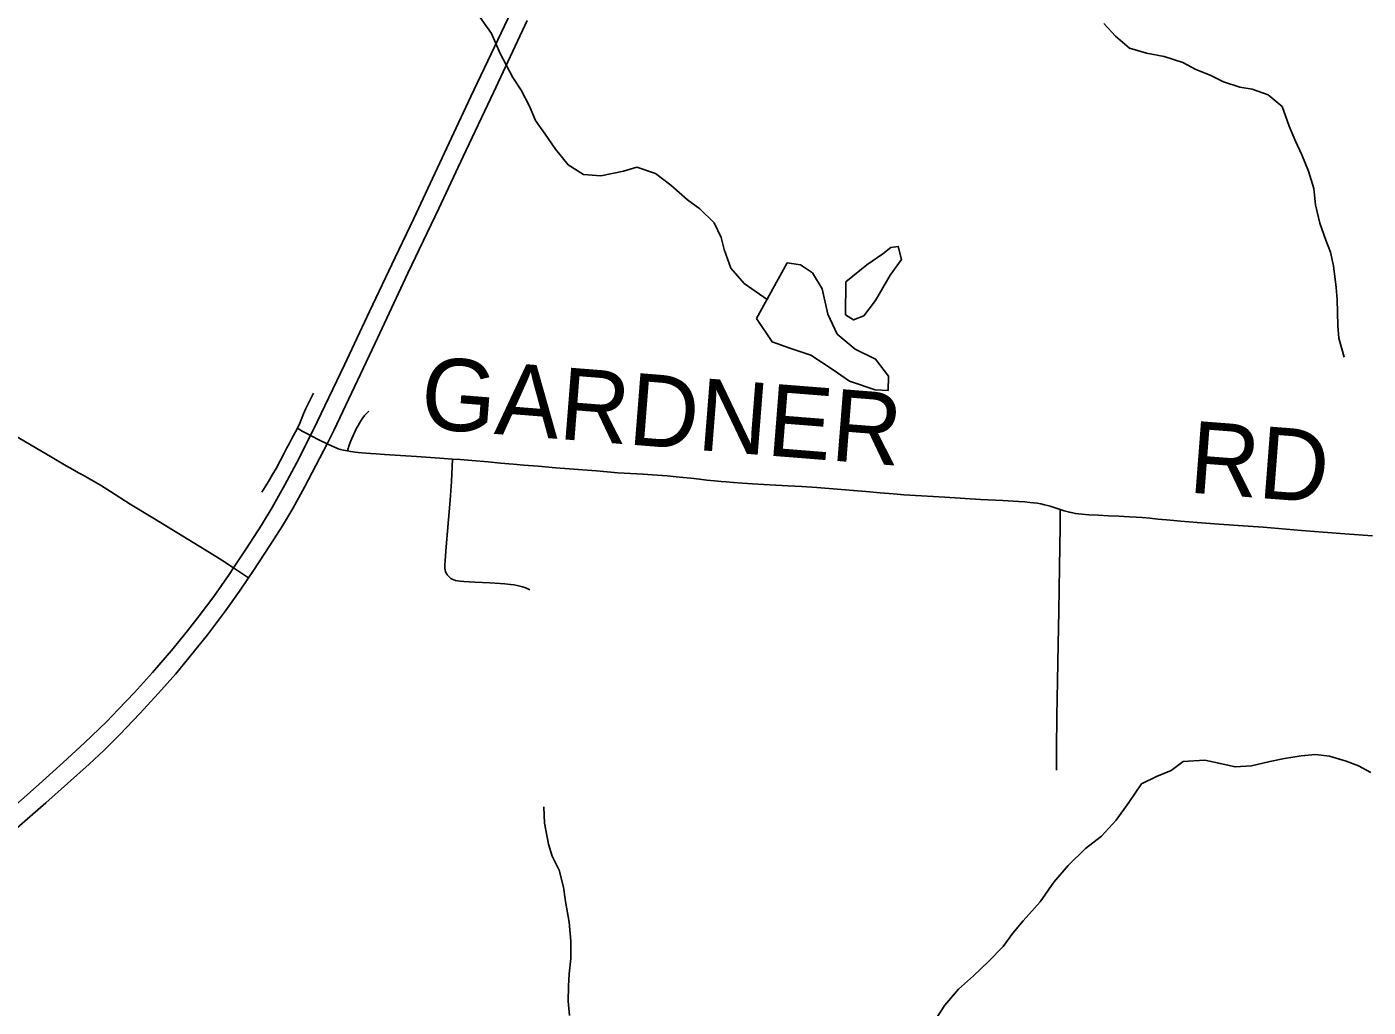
# Model space of a CAD drawing. Extents: x 1451455 to 1749751, y 218250 to 574981.
# Drawn here: x 1595698 to 1601288, y 286670 to 290756 of the extents above; entities that cross this region are included whole.
import ezdxf

# ---------------------------------------------------------------- set-up
doc = ezdxf.new("R2010")
doc.units = 0
for name, color, linetype in [('GM_X_Minor_Lake', 7, 'Continuous'), ('GM_X_Minor_River', 7, 'Continuous'), ('GM_X_Township_Road', 7, 'Continuous'), ('GM_X_Township_Road_Text', 7, 'Continuous'), ('GM_X_Township_ROW', 7, 'Continuous'), ('GM_X_US_Route', 7, 'Continuous')]:
    doc.layers.add(name, color=color, linetype=linetype)

msp = doc.modelspace()

# ---------------------------------------------------------------- linework, layer by layer
at = {"layer": 'GM_X_Minor_Lake'}
for points in [[(1599109.6, 289555.2), (1599143.4, 289534.8), (1599185.6, 289552.2), (1599234.5, 289615.6), (1599295.9, 289720.9), (1599342.7, 289786.4), (1599329.4, 289840.6), (1599299.3, 289837), (1599265, 289809.4), (1599198.3, 289764.3), (1599111.4, 289693.4)], [(1598739.1, 289540.1), (1598803.9, 289443.2), (1598877.6, 289416.2), (1598965.3, 289387), (1599054.7, 289329.7), (1599126.1, 289278.7), (1599233.8, 289243.2), (1599287.8, 289240.5), (1599288.5, 289300.6), (1599235.4, 289371.3), (1599149.8, 289412.5), (1599074.6, 289475.6), (1599035.6, 289558.2), (1599012.9, 289664.6), (1598971.7, 289731.3), (1598922.1, 289764), (1598866.1, 289772.7)], [(1598866.1, 289772.7), (1598739.1, 289540.1)], [(1599111.4, 289693.4), (1599109.6, 289555.2)]]:
    msp.add_lwpolyline(points, dxfattribs=at)
at = {"layer": 'GM_X_Minor_River'}
for points in [[(1597578.2, 290809), (1597635.2, 290728.2), (1597670.2, 290645.6), (1597722.9, 290544.8), (1597758.3, 290492.3), (1597793.5, 290425.8), (1597818.7, 290365.3), (1597858.1, 290308.8), (1597901.3, 290246.1), (1597954.5, 290181.3), (1598018.1, 290140.5), (1598090.1, 290135.5), (1598184.4, 290154.2), (1598240.7, 290171.5), (1598318.4, 290144.4), (1598381.8, 290095.5), (1598451.1, 290034.5), (1598502.7, 289997.8), (1598562, 289939), (1598591.2, 289878.5), (1598604.6, 289828.3), (1598631.7, 289749.8), (1598686.9, 289687), (1598782.8, 289620.2)], [(1600185.9, 290770.2), (1600235.3, 290717.5), (1600292.7, 290666.7), (1600364.5, 290645.7), (1600438.4, 290632.7), (1600516.2, 290607.7), (1600569.8, 290578.9), (1600629.6, 290554.1), (1600685.3, 290527.3), (1600753.1, 290504.4), (1600805, 290495.7), (1600870.8, 290472.8), (1600930.2, 290424), (1600959.2, 290341.5), (1600984.4, 290279.1), (1601011.7, 290222.7), (1601038.9, 290154.2), (1601062, 290081.9), (1601069.1, 290013.7), (1601086.2, 289937.4), (1601111.3, 289867), (1601130.7, 289816.7), (1601144, 289760.4), (1601154.8, 289670.2), (1601158.2, 289620.1), (1601160.8, 289511.9), (1601166.2, 289457.8), (1601187.2, 289379.4)], [(1599472.6, 286598.9), (1599523.6, 286678.3), (1599580.5, 286745.7), (1599643.3, 286800.9), (1599706.1, 286860.1), (1599766.9, 286923.4), (1599807.7, 286978.9), (1599850.3, 287030.4), (1599921.4, 287109.6), (1599978.5, 287190.9), (1600037.4, 287260.2), (1600110.4, 287331.3), (1600177.1, 287382.5), (1600238, 287449.8), (1600290.9, 287523.2), (1600344, 287600.5), (1600406.4, 287631.8), (1600466.8, 287657), (1600517.3, 287694.3), (1600607.4, 287699.2), (1600665.3, 287686.4), (1600733.2, 287671.5), (1600801.3, 287676.5), (1600877.6, 287693.6), (1600939.8, 287706.8), (1601008, 287717.9), (1601068.2, 287723.1), (1601126.1, 287716.3), (1601195.9, 287695.3), (1601247.7, 287676.6), (1601299.4, 287647.9)], [(1597959.7, 286635.2), (1597954.5, 286695.3), (1597955.2, 286757.4), (1597957.9, 286809.4), (1597964.7, 286873.4), (1597965.6, 286945.5), (1597958.6, 287023.7), (1597943.7, 287110), (1597934.4, 287170.2), (1597917.3, 287240.5), (1597888, 287299), (1597872.6, 287349.2), (1597855.7, 287437.5), (1597852.6, 287505.7)]]:
    msp.add_lwpolyline(points, dxfattribs=at)
at = {"layer": 'GM_X_Township_Road'}
for points in [[(1596825.6, 289082.8), (1596835.6, 289104.5), (1596843.7, 289124.5), (1596851.1, 289142.7), (1596861.5, 289164.9), (1596893, 289228.7)], [(1597034.3, 288988.5), (1597037.5, 288999), (1597041.4, 289012), (1597045.3, 289023.7), (1597048.3, 289031.1), (1597052.2, 289039.8), (1597059.6, 289056.2), (1597066.6, 289071), (1597072.2, 289082.7), (1597077.4, 289092.3), (1597083.9, 289104), (1597090, 289114), (1597099.1, 289127), (1597106.1, 289136.1), (1597111.7, 289142.6), (1597116.5, 289147.4), (1597123.6, 289154.2)], [(1595638.7, 289058.4), (1595715.7, 289013.1), (1595796.7, 288964.6), (1595862.7, 288926.5), (1595890, 288910.8), (1595914.1, 288897.8), (1595929.9, 288888.7), (1595949.5, 288877.4), (1595975.5, 288862.6), (1596004.7, 288845.2), (1596046.3, 288819.2), (1596129.6, 288766.7), (1596229.8, 288705.1), (1596373.5, 288617.4), (1596459.4, 288564.9), (1596511.1, 288533.2), (1596560.1, 288501.9)], [(1596678.2, 288816.4), (1596706, 288861.3), (1596722.3, 288889.7), (1596737.1, 288915.6), (1596754.4, 288947), (1596769.6, 288976.5), (1596781.7, 289000.8), (1596790.9, 289018.6), (1596801.3, 289037.3), (1596825.6, 289082.8)], [(1596880, 289053), (1596862.4, 289062), (1596845.5, 289071.1), (1596825.6, 289082.8)], [(1596949.8, 289017.9), (1596918.2, 289033.9), (1596880, 289053)], [(1597034.3, 288988.5), (1597017.4, 288991.9), (1597005.2, 288994.9), (1596996.1, 288997.9), (1596987.8, 289001), (1596980.1, 289004.2), (1596949.8, 289017.9)], [(1597472.1, 288954.7), (1597418.9, 288958.4), (1597322.5, 288965.4), (1597188.8, 288974.1), (1597153.7, 288976.3), (1597130.2, 288978), (1597093.8, 288980.6), (1597079.5, 288981.9), (1597066.4, 288983.2), (1597058.2, 288984.5), (1597046.9, 288986.2), (1597034.3, 288988.5)], [(1597450.4, 288472.2), (1597446.9, 288477.5), (1597444.7, 288481.4), (1597442.5, 288485.7), (1597441.3, 288490.9), (1597440.4, 288498.7), (1597440.4, 288512.2), (1597441.3, 288531.7), (1597445.6, 288588.6), (1597451.7, 288653.7), (1597462.5, 288783), (1597467.3, 288860.7), (1597472.1, 288954.7)], [(1600004.3, 288744.4), (1599995.8, 288747.4), (1599979.6, 288752.7), (1599963.1, 288758), (1599951, 288761.4), (1599938.8, 288764.4), (1599923.6, 288767.5), (1599908.4, 288770.1), (1599893.2, 288772.3), (1599878, 288774), (1599856.8, 288775.7), (1599830.3, 288777.5), (1599765.2, 288781.8), (1599672.3, 288786.6), (1599523.4, 288795.3), (1599427.1, 288800.9), (1599353.3, 288805.7), (1599325.5, 288807.9), (1599289.9, 288810.9), (1599254.8, 288813.9), (1599194, 288819.6), (1599075.5, 288829.5), (1598990.5, 288835.6), (1598928.4, 288840), (1598870.2, 288843.5), (1598819.9, 288846), (1598769.1, 288848.6), (1598722.2, 288851.3), (1598680.6, 288853.9), (1598643.7, 288856.5), (1598612.4, 288859.1), (1598591.6, 288860.8), (1598564.3, 288863.8), (1598532.6, 288867.3), (1598500.9, 288870.8), (1598464.7, 288874.6), (1598433.6, 288877.7), (1598404.1, 288880.8), (1598366.8, 288884.1), (1598324.7, 288887.3), (1598266.1, 288891.2), (1598161.5, 288897.7), (1598072.5, 288905.1), (1597995.2, 288910.7), (1597903.2, 288918.5), (1597829, 288924.6), (1597768.7, 288929.8), (1597724.4, 288933.7), (1597671.9, 288938.1), (1597621.1, 288942.4), (1597552.1, 288948.5), (1597503.9, 288952.4), (1597472.1, 288954.7)], [(1601305.6, 288634.7), (1601190.3, 288643.4), (1601010.5, 288657.3), (1600850.4, 288670.3), (1600745.7, 288678.2), (1600647.6, 288684.9), (1600612, 288687.6), (1600575.6, 288690.3), (1600540.8, 288692.8), (1600505.7, 288695.9), (1600477.5, 288698.5), (1600448.1, 288701), (1600411.9, 288704.5), (1600378.1, 288707.6), (1600345.9, 288710.6), (1600321.6, 288712.3), (1600293.4, 288714.1), (1600249.1, 288716.3), (1600206.2, 288718), (1600162.8, 288720.2), (1600124.1, 288722.8), (1600094.2, 288724.9), (1600080.7, 288726.3), (1600068.6, 288728), (1600057.3, 288730.2), (1600043, 288733.2), (1600032.6, 288735.8), (1600021.7, 288738.8), (1600009.1, 288742.8), (1600004.3, 288744.4)], [(1596560.1, 288501.9), (1596589.2, 288482.4), (1596622.7, 288459.6)], [(1597794.1, 288409.8), (1597782.8, 288415), (1597772.9, 288418.9), (1597763.7, 288421.9), (1597752.9, 288424.9), (1597741.2, 288427.6), (1597728.6, 288430.2), (1597714.3, 288432.3), (1597690.8, 288434.5), (1597671.3, 288435.8), (1597627.4, 288438.4), (1597565.4, 288441.9), (1597541.9, 288443.2), (1597519.4, 288444.5), (1597504.2, 288445.8), (1597492.9, 288447.1), (1597484.7, 288448.8), (1597477.7, 288451), (1597470.8, 288454), (1597465.5, 288457.1), (1597461.2, 288460.5), (1597458.2, 288463.6), (1597453.8, 288468.4), (1597450.4, 288472.2)]]:
    msp.add_lwpolyline(points, dxfattribs=at)
at = {"layer": 'GM_X_Township_ROW'}
msp.add_lwpolyline([(1599988.9, 287658), (1599989.7, 287743.9), (1599990.1, 287884.3), (1599993.8, 288028.6), (1599996.6, 288182.9), (1599999.3, 288320.7), (1600001.5, 288504.3), (1600004.1, 288674), (1600004.3, 288744.4)], dxfattribs=at)
at = {"layer": 'GM_X_US_Route'}
for points in [[(1595602.2, 287469.5), (1595750, 287599.5), (1595850.2, 287689.4), (1595939.1, 287772.2), (1596031, 287861.4), (1596079.5, 287910.5), (1596147, 287982.2), (1596221.6, 288065.3), (1596300.9, 288157.3), (1596367.7, 288238.5), (1596416.2, 288300.6), (1596476.9, 288382.4), (1596541.3, 288473.6), (1596560.1, 288501.9), (1596612.4, 288580.1), (1596676.4, 288679.5), (1596720.2, 288752.9), (1596773.4, 288847.3), (1596821.4, 288937.1), (1596880, 289053), (1596908.7, 289110), (1597021.9, 289346.8), (1597126.3, 289569.5), (1597233.8, 289794.3), (1597310.5, 289957.7), (1597486.9, 290335), (1597548.4, 290465.5), (1597759.1, 290910)], [(1595602.2, 287368.8), (1595777.7, 287521.9), (1595958.7, 287683.5), (1596020.9, 287741.6), (1596085.9, 287806.4), (1596169.8, 287893.9), (1596247.5, 287978.3), (1596318.8, 288059.6), (1596392.1, 288147.8), (1596450.8, 288222.5), (1596525.8, 288322), (1596585.1, 288404.4), (1596622.7, 288459.6), (1596640.4, 288485.7), (1596714.3, 288597.9), (1596763.1, 288675.6), (1596806.6, 288748.9), (1596855.8, 288837.7), (1596919.8, 288959.6), (1596949.8, 289017.9), (1596977, 289073.9), (1597150.3, 289438.1), (1597286.4, 289729.3), (1597414.6, 289998.8), (1597516, 290215.7), (1597643.2, 290482), (1597782.7, 290782.4)]]:
    msp.add_lwpolyline(points, dxfattribs=at)

# ---------------------------------------------------------------- texts
at = {"layer": 'GM_X_Township_Road_Text'}
for s, rotation, p in [('GARDNER', 355.4821, (1597332.3, 289084.3)), ('RD', 355.6076, (1600535.4, 288815.4))]:
    msp.add_text(s, height=300, rotation=rotation, dxfattribs=at).set_placement(p)

doc.saveas('drawing.dxf')
